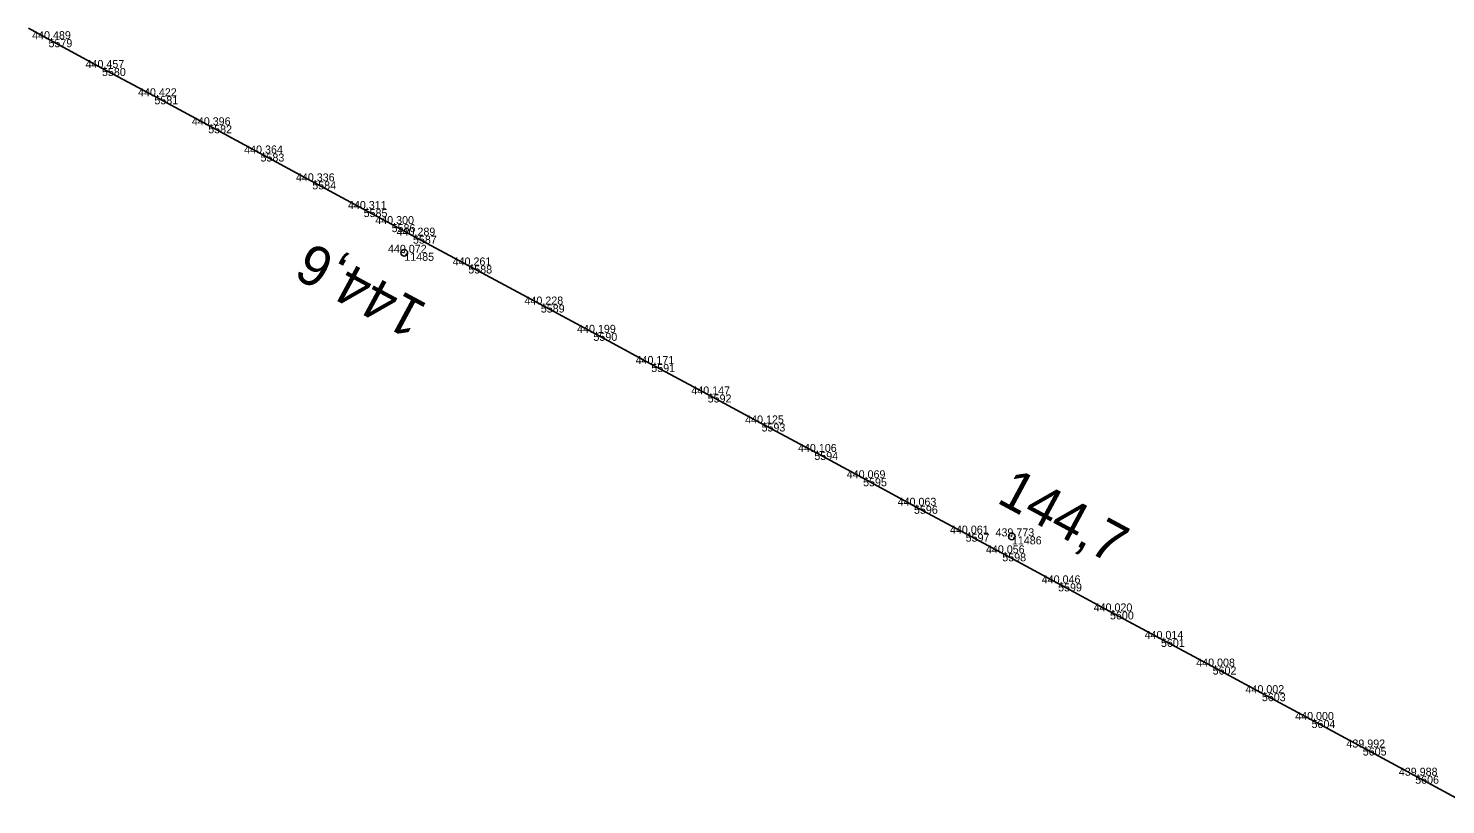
# Model space of a CAD drawing. Extents: x -654154 to -652650, y -1166925 to -1164904.
# Drawn here: x -653488.8 to -653276.3, y -1166838.4 to -1166722 of the extents above; entities that cross this region are included whole.
import ezdxf

# ---------------------------------------------------------------- set-up
doc = ezdxf.new("R2010")
doc.units = 0
for name, color, linetype in [('Vrstva 1', 7, 'Continuous'), ('Vrstva 60', 7, 'Continuous'), ('Vrstva 61', 7, 'Continuous'), ('Vrstva 7', 7, 'Continuous')]:
    doc.layers.add(name, color=color, linetype=linetype)

msp = doc.modelspace()

# ---------------------------------------------------------------- linework, layer by layer
at = {"layer": 'Vrstva 1'}
msp.add_lwpolyline([(-653488.78, -1166721.95), (-653485.76, -1166723.58), (-653477.74, -1166727.9), (-653469.88, -1166732.14), (-653461.81, -1166736.49), (-653453.97, -1166740.72), (-653446.21, -1166744.9), (-653438.51, -1166749.05), (-653434.31, -1166751.31), (-653431.11, -1166753.04), (-653422.81, -1166757.51), (-653411.94, -1166763.37), (-653404.05, -1166767.61), (-653395.38, -1166772.29), (-653386.92, -1166776.85), (-653378.85, -1166781.2), (-653370.93, -1166785.47), (-653363.62, -1166789.42), (-653355.99, -1166793.54), (-653348.24, -1166797.72), (-653342.75, -1166800.67), (-653334.38, -1166805.18), (-653326.6, -1166809.38), (-653318.96, -1166813.5), (-653311.21, -1166817.65), (-653303.83, -1166821.64), (-653296.38, -1166825.66), (-653288.7, -1166829.79), (-653280.84, -1166834.02), (-653272.79, -1166838.36)], dxfattribs=at)
at = {"layer": 'Vrstva 60'}
for p, q in [((-653485.76, -1166723.58), (-653485.76, -1166723.58)), ((-653477.74, -1166727.9), (-653477.74, -1166727.9)), ((-653469.88, -1166732.14), (-653469.88, -1166732.14)), ((-653461.81, -1166736.49), (-653461.81, -1166736.49)), ((-653453.97, -1166740.72), (-653453.97, -1166740.72)), ((-653446.21, -1166744.9), (-653446.21, -1166744.9)), ((-653438.51, -1166749.05), (-653438.51, -1166749.05)), ((-653434.31, -1166751.31), (-653434.31, -1166751.31)), ((-653431.11, -1166753.04), (-653431.11, -1166753.04)), ((-653432.41, -1166755.61), (-653432.41, -1166755.61)), ((-653422.81, -1166757.51), (-653422.81, -1166757.51)), ((-653411.94, -1166763.37), (-653411.94, -1166763.37)), ((-653404.05, -1166767.61), (-653404.05, -1166767.61)), ((-653395.38, -1166772.29), (-653395.38, -1166772.29)), ((-653386.92, -1166776.85), (-653386.92, -1166776.85)), ((-653378.85, -1166781.2), (-653378.85, -1166781.2)), ((-653370.93, -1166785.47), (-653370.93, -1166785.47)), ((-653363.62, -1166789.42), (-653363.62, -1166789.42)), ((-653355.99, -1166793.54), (-653355.99, -1166793.54)), ((-653348.24, -1166797.72), (-653348.24, -1166797.72)), ((-653341.31, -1166798.13), (-653341.31, -1166798.13)), ((-653342.75, -1166800.67), (-653342.75, -1166800.67)), ((-653334.38, -1166805.18), (-653334.38, -1166805.18)), ((-653326.6, -1166809.38), (-653326.6, -1166809.38)), ((-653318.96, -1166813.5), (-653318.96, -1166813.5)), ((-653311.21, -1166817.65), (-653311.21, -1166817.65)), ((-653303.83, -1166821.64), (-653303.83, -1166821.64)), ((-653296.38, -1166825.66), (-653296.38, -1166825.66)), ((-653288.7, -1166829.79), (-653288.7, -1166829.79)), ((-653280.84, -1166834.02), (-653280.84, -1166834.02))]:
    msp.add_line(p, q, dxfattribs=at)
at = {"layer": 'Vrstva 7'}
for p, q in [((-653432.37, -1166755.63), (-653432.46, -1166755.58)), ((-653341.35, -1166798.11), (-653341.26, -1166798.16))]:
    msp.add_line(p, q, dxfattribs=at)
for centre in [(-653432.41, -1166755.61), (-653341.31, -1166798.13)]:
    msp.add_circle(centre, 0.5, dxfattribs=at)

# ---------------------------------------------------------------- texts
at = {"layer": 'Vrstva 60'}
for s, p in [('5579', (-653485.76, -1166724.78)), ('5580', (-653477.74, -1166729.1)), ('5581', (-653469.88, -1166733.34)), ('5582', (-653461.81, -1166737.69)), ('5583', (-653453.97, -1166741.92)), ('5584', (-653446.21, -1166746.1)), ('5585', (-653438.51, -1166750.25)), ('5586', (-653434.31, -1166752.51)), ('5587', (-653431.11, -1166754.24)), ('11485', (-653432.41, -1166756.81)), ('5588', (-653422.81, -1166758.71)), ('5589', (-653411.94, -1166764.57)), ('5590', (-653404.05, -1166768.81)), ('5591', (-653395.38, -1166773.49)), ('5592', (-653386.92, -1166778.05)), ('5593', (-653378.85, -1166782.4)), ('5594', (-653370.93, -1166786.67)), ('5595', (-653363.62, -1166790.62)), ('5596', (-653355.99, -1166794.74)), ('5597', (-653348.24, -1166798.92)), ('11486', (-653341.31, -1166799.33)), ('5598', (-653342.75, -1166801.87)), ('5599', (-653334.38, -1166806.38)), ('5600', (-653326.6, -1166810.58)), ('5601', (-653318.96, -1166814.7)), ('5602', (-653311.21, -1166818.85)), ('5603', (-653303.83, -1166822.84)), ('5604', (-653296.38, -1166826.86)), ('5605', (-653288.7, -1166830.99)), ('5606', (-653280.84, -1166835.22))]:
    msp.add_text(s, height=1.2, dxfattribs=at).set_placement(p)
at = {"layer": 'Vrstva 61'}
for s, p in [('440.489', (-653488.21, -1166723.58)), ('440.457', (-653480.2, -1166727.9)), ('440.422', (-653472.33, -1166732.14)), ('440.396', (-653464.26, -1166736.49)), ('440.364', (-653456.42, -1166740.72)), ('440.336', (-653448.66, -1166744.9)), ('440.311', (-653440.86, -1166749.05)), ('440.300', (-653436.76, -1166751.31)), ('440.289', (-653433.56, -1166753.04)), ('440.072', (-653434.86, -1166755.61)), ('440.261', (-653425.16, -1166757.51)), ('440.228', (-653414.39, -1166763.37)), ('440.199', (-653406.5, -1166767.61)), ('440.171', (-653397.73, -1166772.29)), ('440.147', (-653389.37, -1166776.85)), ('440.125', (-653381.3, -1166781.2)), ('440.106', (-653373.38, -1166785.47)), ('440.069', (-653366.07, -1166789.42)), ('440.063', (-653358.44, -1166793.54)), ('440.061', (-653350.59, -1166797.72)), ('439.773', (-653343.76, -1166798.13)), ('440.056', (-653345.2, -1166800.67)), ('440.046', (-653336.83, -1166805.18)), ('440.020', (-653329.05, -1166809.38)), ('440.014', (-653321.41, -1166813.5)), ('440.008', (-653313.67, -1166817.65)), ('440.002', (-653306.28, -1166821.64)), ('440.000', (-653298.83, -1166825.66)), ('439.992', (-653291.15, -1166829.79)), ('439.988', (-653283.29, -1166834.02))]:
    msp.add_text(s, height=1.2, dxfattribs=at).set_placement(p)
at = {"layer": 'Vrstva 7'}
for s, rotation, p in [('144,6', 151.682, (-653428.71, -1166763.44)), ('144,7', 331.709, (-653343.77, -1166792.97))]:
    msp.add_text(s, height=6, rotation=rotation, dxfattribs=at).set_placement(p)

doc.saveas('drawing.dxf')
